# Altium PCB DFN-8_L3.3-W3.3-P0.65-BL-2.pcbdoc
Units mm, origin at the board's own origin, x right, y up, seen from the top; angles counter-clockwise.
Board outline 16.06 x 16.67 mm, 2 copper layers (Top Layer, Bottom Layer), stack 0 mm thick; 1 components, 0 nets, 5 pads, 0 vias.
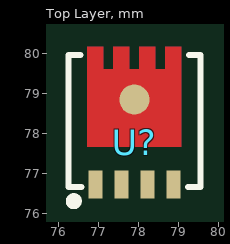
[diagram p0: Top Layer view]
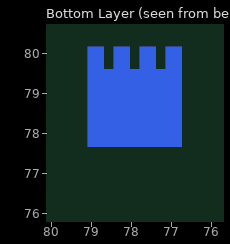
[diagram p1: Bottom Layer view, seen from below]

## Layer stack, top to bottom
Top Layer: signal copper (thickness not stored)
Bottom Layer: signal copper (thickness not stored)

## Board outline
85.91,69.85 69.85,69.85 69.85,86.515 85.91,86.515

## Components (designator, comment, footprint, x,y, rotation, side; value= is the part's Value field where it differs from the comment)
U? "" DFN-8_L3.3-W3.3-P0.65-BL-2 77.905,77.48 r0 top

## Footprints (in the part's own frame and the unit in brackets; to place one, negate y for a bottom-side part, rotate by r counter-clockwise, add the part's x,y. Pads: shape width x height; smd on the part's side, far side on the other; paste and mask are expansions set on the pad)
DFN-8_L3.3-W3.3-P0.65-BL-2 [mm]
  rect 0.35x0.7 smd paste-100 mask+0.051: 1(-0.975,-0.765) 2(-0.325,-0.765) 3(0.325,-0.765) 4(0.975,-0.765)
  round 0.754 smd: 5(0,1.361)
  Top Layer region: -1.176,0.187 -1.176,2.115 -1.176,2.685 -0.775,2.685 -0.775,2.115 -0.526,2.115 -0.526,2.685 -0.125,2.685 -0.125,2.115 0.125,2.115 0.125,2.685 0.525,2.685 0.525,2.115 0.774,2.115 0.774,2.685 0.774,2.115 0.774,2.685 1.176,2.685 1.176,2.115 1.176,0.187
  Bottom Layer region: -1.176,0.187 -1.176,2.115 -1.176,2.685 -0.775,2.685 -0.775,2.115 -0.526,2.115 -0.526,2.685 -0.125,2.685 -0.125,2.115 0.125,2.115 0.125,2.685 0.525,2.685 0.525,2.115 0.774,2.115 0.774,2.685 0.774,2.115 0.774,2.685 1.176,2.685 1.176,2.115 1.176,0.187
  Multi-Layer region: -1.176,0.187 -1.176,2.115 -1.176,2.685 -0.775,2.685 -0.775,2.115 -0.526,2.115 -0.526,2.685 -0.125,2.685 -0.125,2.115 0.125,2.115 0.125,2.685 0.525,2.685 0.525,2.115 0.774,2.115 0.774,2.685 0.774,2.115 0.774,2.685 1.176,2.685 1.176,2.115 1.176,0.187
  silkscreen extent -1.65,-1.28 1.65,2.48

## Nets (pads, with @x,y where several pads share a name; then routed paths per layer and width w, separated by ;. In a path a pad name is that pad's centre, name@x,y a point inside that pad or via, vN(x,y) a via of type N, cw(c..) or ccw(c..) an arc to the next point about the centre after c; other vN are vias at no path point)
pads on no net: U?.1 U?.2 U?.3 U?.4 U?.5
